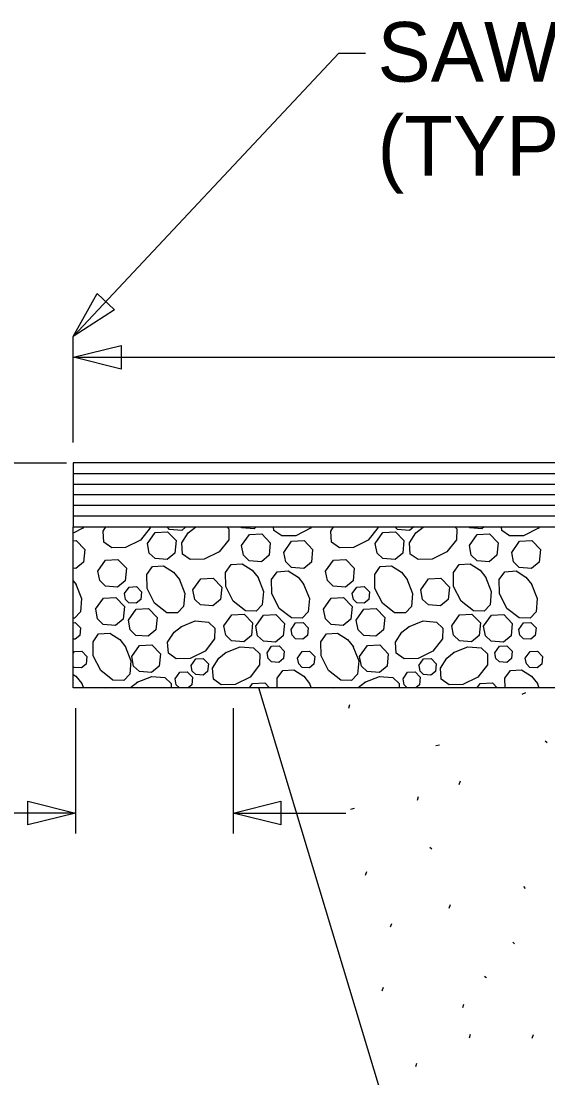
# Model space of a CAD drawing. Extents: x 9937.2 to 10006.2, y 10008.4 to 10068.3.
# Drawn here: x 9962.48 to 9971.7, y 10049.44 to 10067.93 of the extents above; entities that cross this region are included whole.
import ezdxf

# ---------------------------------------------------------------- set-up
doc = ezdxf.new("R2010")
doc.units = 0
for name, color, linetype in [('Default', 7, 'Continuous'), ('G-ANNO-TEXT', 7, 'Continuous'), ('G-DETL-LINE', 7, 'Continuous'), ('G-DETL-OTLN', 7, 'Continuous'), ('G-DETL-PATT', 7, 'Continuous')]:
    doc.layers.add(name, color=color, linetype=linetype)

# ---------------------------------------------------------------- blocks, each defined once
blk = doc.blocks.new('TERARR')
at = {"layer": 'Default'}
blk.add_lwpolyline([(-0.667, 0.167), (0, 0), (-0.667, -0.167)], close=True, dxfattribs=at)

msp = doc.modelspace()

# ---------------------------------------------------------------- linework, layer by layer
at = {"layer": 'Default'}
for points in [[(9965.367, 10059.079), (9965.295, 10059.019), (9965.082, 10059.035), (9965.036, 10059.079)], [(9965.523, 10059.07), (9965.544, 10059.079)], [(9966.598, 10059.079), (9966.561, 10059.048), (9966.348, 10059.064), (9966.333, 10059.079)], [(9969.355, 10059.079), (9969.283, 10059.019), (9969.07, 10059.035), (9969.024, 10059.079)], [(9969.511, 10059.07), (9969.533, 10059.079)], [(9970.586, 10059.079), (9970.55, 10059.048), (9970.336, 10059.064), (9970.321, 10059.079)], [(9963.395, 10058.133), (9963.446, 10058.07)], [(9967.526, 10056.35), (9967.56, 10056.263)], [(9963.953, 10056.263), (9964.084, 10056.271), (9964.092, 10056.263)], [(9967.942, 10056.263), (9968.073, 10056.271), (9968.08, 10056.263)]]:
    msp.add_lwpolyline(points, dxfattribs=at)
at = {"layer": 'G-ANNO-TEXT'}
for p, q in [((9963.395, 10060.558), (9963.395, 10062.413)), ((9963.397, 10062.048), (9986.763, 10062.055)), ((9952.779, 10060.199), (9963.277, 10060.199)), ((9963.435, 10055.906), (9963.435, 10053.713)), ((9966.194, 10055.906), (9966.194, 10053.713)), ((9963.435, 10054.071), (9955.939, 10054.071)), ((9966.194, 10054.071), (9968.166, 10054.071))]:
    msp.add_line(p, q, dxfattribs=at)
msp.add_lwpolyline([(9963.395, 10062.413), (9968.043, 10067.37), (9968.512, 10067.37)], dxfattribs=at)
at = {"layer": 'G-DETL-LINE'}
msp.add_lwpolyline([(9963.395, 10059.079), (9986.763, 10059.079), (9986.763, 10056.263), (9963.395, 10056.263)], close=True, dxfattribs=at)
at = {"layer": 'G-DETL-OTLN'}
msp.add_line((9986.763, 10059.639), (9963.395, 10059.639), dxfattribs=at)
msp.add_lwpolyline([(9963.395, 10059.079), (9986.763, 10059.079), (9986.763, 10060.2), (9963.395, 10060.2)], close=True, dxfattribs=at)
msp.add_lwpolyline([(9984.004, 10056.263), (9978.811, 10039.068), (9978.811, 10035.651), (9971.834, 10035.651), (9971.834, 10039.068), (9966.641, 10056.263)], dxfattribs=at)
at = {"layer": 'G-DETL-PATT'}
for p, q in [((9986.763, 10060.009), (9963.395, 10060.009)), ((9986.763, 10059.824), (9963.395, 10059.824)), ((9986.763, 10059.455), (9963.395, 10059.455)), ((9986.763, 10059.27), (9963.395, 10059.27)), ((9971.311, 10056.178), (9971.248, 10056.147)), ((9968.218, 10055.907), (9968.239, 10055.97)), ((9969.806, 10055.259), (9969.741, 10055.245)), ((9971.689, 10055.298), (9971.658, 10055.33)), ((9970.153, 10054.572), (9970.174, 10054.635)), ((9969.419, 10054.299), (9969.44, 10054.362)), ((9968.311, 10054.148), (9968.247, 10054.134)), ((9969.672, 10053.439), (9969.64, 10053.47)), ((9968.511, 10052.983), (9968.532, 10053.046)), ((9971.311, 10052.753), (9971.28, 10052.785)), ((9969.977, 10052.408), (9969.998, 10052.471)), ((9968.95, 10052.077), (9968.971, 10052.139)), ((9971.122, 10051.779), (9971.091, 10051.811)), ((9970.592, 10051.213), (9970.619, 10051.199)), ((9970.619, 10051.199), (9970.631, 10051.185)), ((9968.805, 10050.958), (9968.826, 10051.021)), ((9970.212, 10050.665), (9970.233, 10050.728)), ((9970.329, 10050.139), (9970.35, 10050.202)), ((9971.431, 10050.129), (9971.452, 10050.192)), ((9969.39, 10049.632), (9969.411, 10049.695))]:
    msp.add_line(p, q, dxfattribs=at)
for points in [[(9963.58, 10059.079), (9963.561, 10059.055), (9963.395, 10058.972)], [(9964.739, 10059.079), (9964.739, 10059.061), (9964.571, 10058.846), (9964.311, 10058.717), (9964.067, 10058.712), (9963.929, 10058.81), (9963.916, 10059.005), (9963.963, 10059.079)], [(9964.693, 10058.79), (9964.829, 10058.983), (9965.045, 10058.995), (9965.196, 10058.839), (9965.174, 10058.62), (9965.04, 10058.509), (9964.827, 10058.525), (9964.726, 10058.622), (9964.693, 10058.79)], [(9966.084, 10059.079), (9966.12, 10059.045), (9966.116, 10058.856), (9965.948, 10058.642), (9965.689, 10058.512), (9965.444, 10058.507), (9965.306, 10058.605), (9965.293, 10058.8), (9965.405, 10058.974), (9965.533, 10059.077)], [(9966.342, 10058.752), (9966.478, 10058.945), (9966.694, 10058.957), (9966.844, 10058.801), (9966.823, 10058.583), (9966.689, 10058.471), (9966.475, 10058.487), (9966.375, 10058.584), (9966.342, 10058.752)], [(9967.568, 10059.079), (9967.549, 10059.055), (9967.29, 10058.925), (9967.045, 10058.921), (9966.907, 10059.018), (9966.903, 10059.079)], [(9968.728, 10059.079), (9968.727, 10059.061), (9968.559, 10058.846), (9968.3, 10058.717), (9968.055, 10058.712), (9967.917, 10058.81), (9967.904, 10059.005), (9967.952, 10059.079)], [(9968.682, 10058.79), (9968.817, 10058.983), (9969.034, 10058.995), (9969.184, 10058.839), (9969.162, 10058.62), (9969.029, 10058.509), (9968.815, 10058.525), (9968.714, 10058.622), (9968.682, 10058.79)], [(9970.073, 10059.079), (9970.108, 10059.045), (9970.105, 10058.856), (9969.937, 10058.642), (9969.677, 10058.512), (9969.432, 10058.507), (9969.295, 10058.605), (9969.282, 10058.8), (9969.393, 10058.974), (9969.521, 10059.077)], [(9970.33, 10058.752), (9970.466, 10058.945), (9970.682, 10058.957), (9970.833, 10058.801), (9970.811, 10058.583), (9970.677, 10058.471), (9970.464, 10058.487), (9970.363, 10058.584), (9970.331, 10058.752)], [(9971.557, 10059.079), (9971.538, 10059.055), (9971.278, 10058.925), (9971.034, 10058.921), (9970.896, 10059.018), (9970.892, 10059.079)], [(9963.395, 10058.836), (9963.446, 10058.839), (9963.597, 10058.683), (9963.575, 10058.465), (9963.441, 10058.353), (9963.395, 10058.357)], [(9967.083, 10058.634), (9967.218, 10058.827), (9967.435, 10058.839), (9967.585, 10058.683), (9967.563, 10058.465), (9967.43, 10058.353), (9967.216, 10058.369), (9967.116, 10058.466), (9967.083, 10058.634)], [(9971.071, 10058.634), (9971.207, 10058.827), (9971.423, 10058.839), (9971.574, 10058.683), (9971.552, 10058.465), (9971.418, 10058.353), (9971.204, 10058.369), (9971.104, 10058.466), (9971.071, 10058.634)], [(9963.824, 10058.306), (9963.96, 10058.499), (9964.176, 10058.511), (9964.327, 10058.355), (9964.305, 10058.137), (9964.171, 10058.026), (9963.958, 10058.041), (9963.857, 10058.139), (9963.825, 10058.306)], [(9965.247, 10058.17), (9965.347, 10057.916), (9965.327, 10057.684), (9965.222, 10057.573), (9965.033, 10057.576), (9964.818, 10057.744), (9964.689, 10058.004), (9964.684, 10058.249), (9964.782, 10058.386), (9964.977, 10058.399), (9965.151, 10058.288), (9965.253, 10058.16)], [(9966.624, 10058.203), (9966.725, 10057.949), (9966.704, 10057.716), (9966.599, 10057.606), (9966.41, 10057.609), (9966.196, 10057.777), (9966.066, 10058.037), (9966.061, 10058.282), (9966.159, 10058.419), (9966.354, 10058.432), (9966.528, 10058.321), (9966.631, 10058.193)], [(9967.813, 10058.306), (9967.948, 10058.499), (9968.165, 10058.511), (9968.315, 10058.355), (9968.293, 10058.137), (9968.16, 10058.026), (9967.946, 10058.041), (9967.845, 10058.139), (9967.813, 10058.306)], [(9969.235, 10058.17), (9969.336, 10057.916), (9969.316, 10057.684), (9969.21, 10057.573), (9969.021, 10057.576), (9968.807, 10057.744), (9968.677, 10058.004), (9968.673, 10058.249), (9968.77, 10058.386), (9968.965, 10058.399), (9969.14, 10058.288), (9969.242, 10058.16)], [(9970.612, 10058.203), (9970.713, 10057.949), (9970.693, 10057.716), (9970.588, 10057.606), (9970.399, 10057.609), (9970.184, 10057.777), (9970.054, 10058.037), (9970.05, 10058.282), (9970.148, 10058.419), (9970.343, 10058.432), (9970.517, 10058.321), (9970.619, 10058.193)], [(9965.49, 10057.978), (9965.626, 10058.171), (9965.842, 10058.183), (9965.993, 10058.027), (9965.971, 10057.809), (9965.837, 10057.698), (9965.623, 10057.713), (9965.523, 10057.811), (9965.49, 10057.978)], [(9967.427, 10058.08), (9967.528, 10057.826), (9967.508, 10057.593), (9967.403, 10057.483), (9967.214, 10057.486), (9966.999, 10057.654), (9966.869, 10057.914), (9966.865, 10058.159), (9966.963, 10058.296), (9967.158, 10058.309), (9967.332, 10058.198), (9967.434, 10058.07)], [(9969.479, 10057.978), (9969.614, 10058.171), (9969.831, 10058.183), (9969.981, 10058.027), (9969.959, 10057.809), (9969.825, 10057.698), (9969.612, 10057.713), (9969.511, 10057.811), (9969.479, 10057.978)], [(9971.416, 10058.08), (9971.516, 10057.826), (9971.496, 10057.593), (9971.391, 10057.483), (9971.202, 10057.486), (9970.987, 10057.654), (9970.857, 10057.914), (9970.853, 10058.159), (9970.951, 10058.296), (9971.146, 10058.309), (9971.32, 10058.198), (9971.422, 10058.07)], [(9963.439, 10058.08), (9963.54, 10057.826), (9963.519, 10057.593), (9963.414, 10057.483), (9963.395, 10057.483)], [(9964.29, 10057.911), (9964.371, 10058.027), (9964.501, 10058.034), (9964.591, 10057.941), (9964.578, 10057.81), (9964.498, 10057.743), (9964.37, 10057.752), (9964.31, 10057.811), (9964.29, 10057.911)], [(9968.278, 10057.911), (9968.36, 10058.027), (9968.489, 10058.034), (9968.58, 10057.941), (9968.567, 10057.81), (9968.486, 10057.743), (9968.358, 10057.752), (9968.298, 10057.811), (9968.278, 10057.911)], [(9963.786, 10057.637), (9963.922, 10057.83), (9964.138, 10057.842), (9964.289, 10057.686), (9964.267, 10057.467), (9964.133, 10057.356), (9963.92, 10057.372), (9963.819, 10057.469), (9963.787, 10057.637)], [(9967.775, 10057.637), (9967.91, 10057.83), (9968.127, 10057.842), (9968.277, 10057.686), (9968.255, 10057.467), (9968.122, 10057.356), (9967.908, 10057.372), (9967.808, 10057.469), (9967.775, 10057.637)], [(9964.359, 10057.445), (9964.495, 10057.638), (9964.711, 10057.65), (9964.861, 10057.495), (9964.84, 10057.276), (9964.706, 10057.165), (9964.492, 10057.18), (9964.392, 10057.278), (9964.359, 10057.445)], [(9968.347, 10057.445), (9968.483, 10057.638), (9968.699, 10057.65), (9968.85, 10057.495), (9968.828, 10057.276), (9968.694, 10057.165), (9968.481, 10057.18), (9968.38, 10057.278), (9968.348, 10057.445)], [(9966.033, 10057.35), (9966.168, 10057.543), (9966.384, 10057.555), (9966.535, 10057.399), (9966.513, 10057.181), (9966.379, 10057.069), (9966.166, 10057.085), (9966.065, 10057.182), (9966.033, 10057.35)], [(9966.59, 10057.342), (9966.726, 10057.534), (9966.942, 10057.547), (9967.092, 10057.391), (9967.071, 10057.172), (9966.937, 10057.061), (9966.723, 10057.077), (9966.623, 10057.174), (9966.59, 10057.342)], [(9970.021, 10057.35), (9970.156, 10057.543), (9970.373, 10057.555), (9970.523, 10057.399), (9970.501, 10057.181), (9970.368, 10057.069), (9970.154, 10057.085), (9970.054, 10057.182), (9970.021, 10057.35)], [(9970.578, 10057.342), (9970.714, 10057.534), (9970.93, 10057.547), (9971.081, 10057.391), (9971.059, 10057.172), (9970.925, 10057.061), (9970.712, 10057.077), (9970.611, 10057.174), (9970.578, 10057.342)], [(9963.395, 10057.403), (9963.429, 10057.405), (9963.52, 10057.312), (9963.507, 10057.181), (9963.426, 10057.114), (9963.395, 10057.116)], [(9965.277, 10057.332), (9965.53, 10057.433), (9965.763, 10057.413), (9965.874, 10057.307), (9965.87, 10057.118), (9965.702, 10056.904), (9965.443, 10056.774), (9965.198, 10056.77), (9965.06, 10056.867), (9965.047, 10057.062), (9965.159, 10057.237), (9965.287, 10057.339)], [(9967.207, 10057.282), (9967.288, 10057.398), (9967.418, 10057.405), (9967.508, 10057.312), (9967.495, 10057.181), (9967.415, 10057.114), (9967.286, 10057.123), (9967.226, 10057.182), (9967.207, 10057.282)], [(9969.265, 10057.332), (9969.519, 10057.433), (9969.751, 10057.413), (9969.862, 10057.307), (9969.859, 10057.118), (9969.691, 10056.904), (9969.431, 10056.774), (9969.186, 10056.77), (9969.049, 10056.867), (9969.036, 10057.062), (9969.147, 10057.237), (9969.275, 10057.339)], [(9971.195, 10057.282), (9971.276, 10057.398), (9971.406, 10057.405), (9971.496, 10057.312), (9971.483, 10057.181), (9971.403, 10057.114), (9971.275, 10057.123), (9971.215, 10057.182), (9971.195, 10057.282)], [(9964.304, 10056.99), (9964.405, 10056.736), (9964.385, 10056.503), (9964.279, 10056.392), (9964.09, 10056.396), (9963.876, 10056.564), (9963.746, 10056.824), (9963.742, 10057.068), (9963.839, 10057.206), (9964.034, 10057.219), (9964.209, 10057.107), (9964.311, 10056.979)], [(9968.292, 10056.99), (9968.393, 10056.736), (9968.373, 10056.503), (9968.268, 10056.392), (9968.079, 10056.396), (9967.864, 10056.564), (9967.734, 10056.824), (9967.73, 10057.068), (9967.828, 10057.206), (9968.023, 10057.219), (9968.197, 10057.107), (9968.299, 10056.979)], [(9963.395, 10056.869), (9963.414, 10056.896), (9963.544, 10056.903), (9963.634, 10056.81), (9963.621, 10056.679), (9963.541, 10056.612), (9963.413, 10056.621), (9963.395, 10056.638)], [(9964.419, 10056.811), (9964.555, 10057.004), (9964.771, 10057.016), (9964.922, 10056.86), (9964.9, 10056.642), (9964.766, 10056.531), (9964.553, 10056.546), (9964.452, 10056.644), (9964.419, 10056.811)], [(9966.063, 10056.879), (9966.317, 10056.98), (9966.55, 10056.96), (9966.66, 10056.855), (9966.657, 10056.666), (9966.489, 10056.451), (9966.229, 10056.321), (9965.984, 10056.317), (9965.847, 10056.415), (9965.834, 10056.609), (9965.945, 10056.784), (9966.073, 10056.886)], [(9966.787, 10056.875), (9966.868, 10056.991), (9966.998, 10056.999), (9967.089, 10056.905), (9967.076, 10056.774), (9966.995, 10056.707), (9966.867, 10056.716), (9966.807, 10056.775), (9966.787, 10056.875)], [(9967.321, 10056.78), (9967.402, 10056.896), (9967.532, 10056.903), (9967.622, 10056.81), (9967.609, 10056.679), (9967.529, 10056.612), (9967.401, 10056.621), (9967.341, 10056.68), (9967.321, 10056.78)], [(9968.408, 10056.811), (9968.543, 10057.004), (9968.76, 10057.016), (9968.91, 10056.86), (9968.888, 10056.642), (9968.755, 10056.531), (9968.541, 10056.546), (9968.44, 10056.644), (9968.408, 10056.811)], [(9970.052, 10056.879), (9970.305, 10056.98), (9970.538, 10056.96), (9970.649, 10056.855), (9970.645, 10056.666), (9970.477, 10056.451), (9970.217, 10056.321), (9969.973, 10056.317), (9969.835, 10056.415), (9969.822, 10056.609), (9969.934, 10056.784), (9970.062, 10056.886)], [(9970.776, 10056.875), (9970.857, 10056.991), (9970.987, 10056.999), (9971.077, 10056.905), (9971.064, 10056.774), (9970.984, 10056.707), (9970.855, 10056.716), (9970.795, 10056.775), (9970.776, 10056.875)], [(9971.309, 10056.78), (9971.391, 10056.896), (9971.52, 10056.903), (9971.611, 10056.81), (9971.598, 10056.679), (9971.517, 10056.612), (9971.389, 10056.621), (9971.329, 10056.68), (9971.309, 10056.78)], [(9965.459, 10056.653), (9965.54, 10056.769), (9965.67, 10056.776), (9965.761, 10056.683), (9965.747, 10056.551), (9965.667, 10056.485), (9965.539, 10056.494), (9965.479, 10056.553), (9965.459, 10056.653)], [(9969.447, 10056.653), (9969.529, 10056.769), (9969.659, 10056.776), (9969.749, 10056.683), (9969.736, 10056.551), (9969.656, 10056.485), (9969.527, 10056.494), (9969.467, 10056.553), (9969.448, 10056.653)], [(9965.18, 10056.418), (9965.261, 10056.534), (9965.391, 10056.541), (9965.481, 10056.447), (9965.468, 10056.316), (9965.404, 10056.263)], [(9966.966, 10056.263), (9966.963, 10056.429), (9967.061, 10056.567), (9967.256, 10056.58), (9967.43, 10056.468), (9967.532, 10056.34)], [(9969.168, 10056.418), (9969.249, 10056.534), (9969.379, 10056.541), (9969.469, 10056.447), (9969.456, 10056.316), (9969.393, 10056.263)], [(9970.954, 10056.263), (9970.951, 10056.429), (9971.049, 10056.567), (9971.244, 10056.58), (9971.419, 10056.468), (9971.521, 10056.34)], [(9963.395, 10056.498), (9963.442, 10056.468), (9963.544, 10056.34)], [(9963.537, 10056.35), (9963.572, 10056.263)], [(9964.394, 10056.263), (9964.396, 10056.267), (9964.524, 10056.369)], [(9964.514, 10056.363), (9964.768, 10056.463), (9965, 10056.443), (9965.111, 10056.338), (9965.11, 10056.263)], [(9965.255, 10056.263), (9965.199, 10056.317), (9965.18, 10056.418)], [(9966.479, 10056.263), (9966.531, 10056.336), (9966.747, 10056.349), (9966.829, 10056.263)], [(9968.382, 10056.263), (9968.385, 10056.267), (9968.513, 10056.369)], [(9968.502, 10056.363), (9968.756, 10056.463), (9968.989, 10056.443), (9969.099, 10056.338), (9969.098, 10056.263)], [(9969.243, 10056.263), (9969.188, 10056.317), (9969.168, 10056.418)], [(9970.468, 10056.263), (9970.519, 10056.336), (9970.735, 10056.349), (9970.818, 10056.263)], [(9971.514, 10056.35), (9971.548, 10056.263)]]:
    msp.add_lwpolyline(points, dxfattribs=at)

# ---------------------------------------------------------------- block references
at = {"layer": 'G-ANNO-TEXT', "xscale": 1.25, "yscale": 1.25}
for p, rotation in [((9963.395, 10062.413), -133.15892459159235), ((9963.397, 10062.048), -179.98090940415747), ((9966.194, 10054.071), 180)]:
    msp.add_blockref('TERARR', p, dxfattribs=dict(at, rotation=rotation))
msp.add_blockref('TERARR', (9963.435, 10054.071), dxfattribs=at)

# ---------------------------------------------------------------- texts
at = {"layer": 'G-ANNO-TEXT'}
for s, p in [('SAWCUT', (9968.722, 10066.873)), ('(TYP.)', (9968.722, 10065.229))]:
    msp.add_text(s, height=1.044, dxfattribs=at).set_placement(p)

doc.saveas('drawing.dxf')
